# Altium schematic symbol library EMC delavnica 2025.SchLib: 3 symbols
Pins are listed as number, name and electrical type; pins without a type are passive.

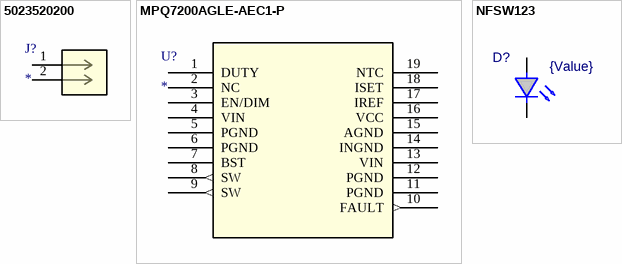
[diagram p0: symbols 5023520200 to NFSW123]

## 5023520200
designator J?
No Description Available; Mfr_Name: Molex Connector Corporation
footprint CONN02_502352_MOL
pins: 1, 2

## MPQ7200AGLE-AEC1-P
designator U?
No Description Available; Mfr_Name: Monolithic Power Systems
footprint QFN-19_MPQ7200A_MNP
pins: 1 DUTY, 2 NC, 3 EN/DIM, 4 VIN (power), 5 PGND (power), 6 PGND (power), 7 BST (power), 8 SW (out), 9 SW (out), 10 FAULT (out), 11 PGND (power), 12 PGND (power), 13 VIN (power), 14 INGND (power), 15 AGND (power), 16 VCC (power), 17 IREF, 18 ISET, 19 NTC

## NFSW123
designator D?  value {Value}  (hidden comment: *)
Chip LED diode
footprint NFSW123G
pins: A, K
